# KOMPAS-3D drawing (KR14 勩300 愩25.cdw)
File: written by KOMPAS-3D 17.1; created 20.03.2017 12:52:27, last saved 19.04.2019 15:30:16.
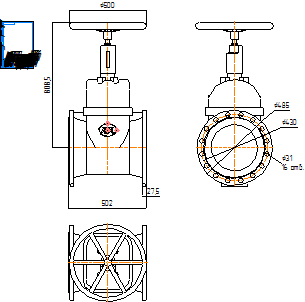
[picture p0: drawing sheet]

Sheet 1: A4, portrait

Title block, sheet 1: name: KR14 Ду300 Ру25; material: Внимание! Данный продукт является объектом авторского права ООО «Торговый Дом АДЛ». / Запрещается изменение, копирование, распространение / (в том числе путем копирования на другие сайты и ресурсы в Интернете) / или любое иное использование информации и объектов без предварительного / согласия правообладателя (ООО «Торговый Дом АДЛ»).; mass: 508; sheets: 1; organisation: ООО "Торговый дом АДЛ"; sheet format: A4; stored path: C:\Users\kka\KOMPAS_Work\!Trash\Задвижки ГРАНАР с приводами\KR14 Ду350 Ру16.cdw

Views: Вид 1, Проекционный вид 2, Проекционный вид 3
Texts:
  Klimkovich
  ADL
Dimensions and other numbers on the sheet: 500; 808,5; 485; 430; 31; 16 отв.; 502; 27,5; 1:1; 1; 508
